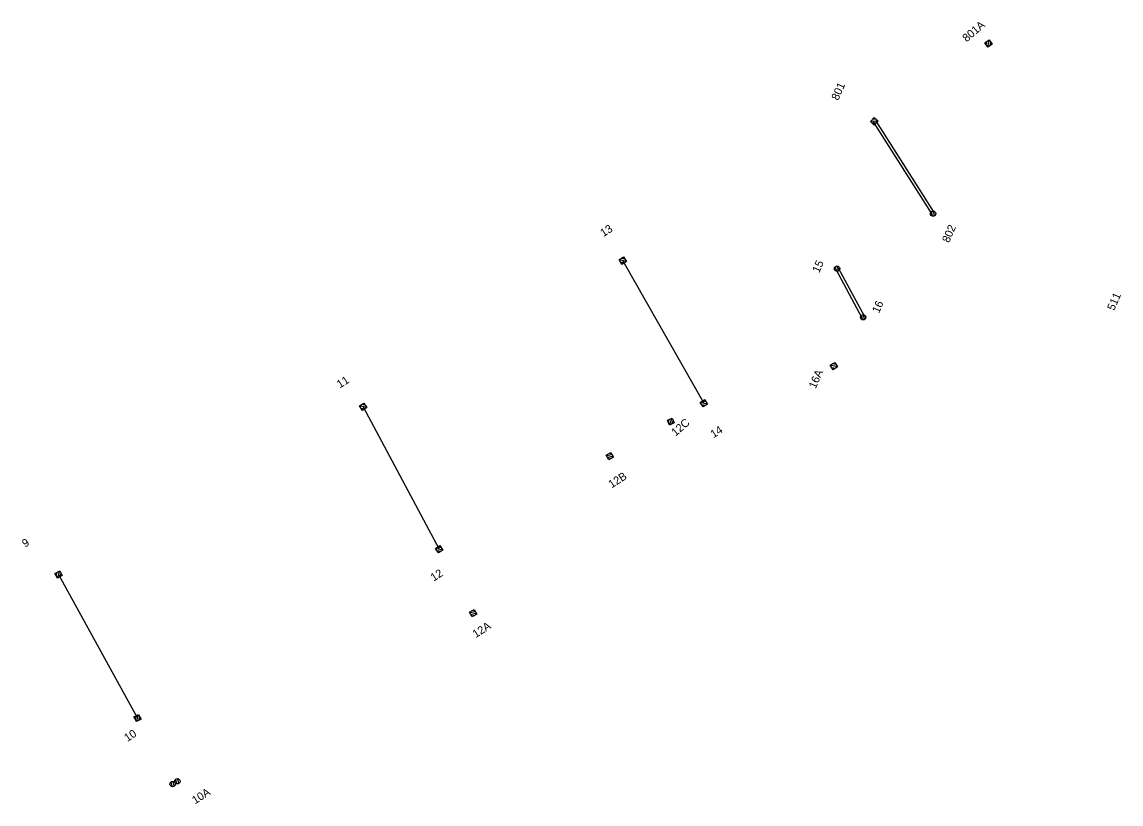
# Model space of a CAD drawing. Extents: x -595867 to -593796, y -1159595 to -1157495.
# Drawn here: x -595653.3 to -595447.3, y -1159453 to -1159306.6 of the extents above; entities that cross this region are included whole.
import ezdxf

# ---------------------------------------------------------------- set-up
doc = ezdxf.new("R2010")
doc.units = 0
doc.layers.add('BVK_kanalizace_jednotna_nova', color=7, linetype='Continuous')

msp = doc.modelspace()

# ---------------------------------------------------------------- linework, layer by layer
at = {"layer": 'BVK_kanalizace_jednotna_nova'}
for p, q in [((-595472.61, -1159310.84), (-595472.48, -1159310.19)), ((-595472.32, -1159311.28), (-595472.04, -1159309.9)), ((-595471.88, -1159310.99), (-595471.75, -1159310.34)), ((-595492.86, -1159325.15), (-595494.27, -1159325.17)), ((-595493.24, -1159324.78), (-595493.91, -1159324.79)), ((-595493.23, -1159325.53), (-595493.89, -1159325.54)), ((-595482.66, -1159342.92), (-595482.82, -1159342.02)), ((-595482.29, -1159342.86), (-595482.45, -1159341.95)), ((-595540.02, -1159351.41), (-595541.4, -1159351.11)), ((-595540.47, -1159351.7), (-595541.11, -1159351.56)), ((-595540.3, -1159350.97), (-595540.96, -1159350.82)), ((-595500.65, -1159353.23), (-595500.81, -1159352.33)), ((-595500.28, -1159353.18), (-595500.44, -1159352.26)), ((-595495.76, -1159362.34), (-595495.92, -1159361.44)), ((-595495.39, -1159362.28), (-595495.56, -1159361.37)), ((-595500.43, -1159371.15), (-595501.81, -1159370.85)), ((-595500.88, -1159371.44), (-595501.52, -1159371.3)), ((-595500.71, -1159370.71), (-595501.37, -1159370.56)), ((-595588.65, -1159378.77), (-595590.03, -1159378.47)), ((-595589.1, -1159379.06), (-595589.74, -1159378.92)), ((-595588.93, -1159378.33), (-595589.59, -1159378.18)), ((-595524.8, -1159378.11), (-595526.18, -1159377.81)), ((-595525.25, -1159378.4), (-595525.89, -1159378.26)), ((-595525.08, -1159377.67), (-595525.74, -1159377.52)), ((-595532.17, -1159381.54), (-595531.91, -1159380.93)), ((-595531.96, -1159382.03), (-595531.42, -1159380.73)), ((-595531.47, -1159381.83), (-595531.22, -1159381.22)), ((-595542.42, -1159388.07), (-595543.78, -1159387.67)), ((-595542.67, -1159387.61), (-595543.31, -1159387.42)), ((-595542.89, -1159388.32), (-595543.52, -1159388.14)), ((-595574.4, -1159405.45), (-595575.78, -1159405.15)), ((-595574.85, -1159405.74), (-595575.49, -1159405.6)), ((-595574.68, -1159405.01), (-595575.34, -1159404.86)), ((-595646.86, -1159410.24), (-595646.67, -1159409.61)), ((-595646.6, -1159410.7), (-595646.2, -1159409.35)), ((-595646.14, -1159410.45), (-595645.95, -1159409.81)), ((-595568.06, -1159417.46), (-595569.42, -1159417.06)), ((-595568.53, -1159417.71), (-595569.16, -1159417.53)), ((-595568.31, -1159417), (-595568.96, -1159416.81)), ((-595632.07, -1159437.11), (-595631.88, -1159436.48)), ((-595631.82, -1159437.58), (-595631.41, -1159436.23)), ((-595631.36, -1159437.34), (-595631.16, -1159436.7)), ((-595625.14, -1159449.74), (-595625.3, -1159448.84)), ((-595624.77, -1159449.68), (-595624.94, -1159448.77)), ((-595624.26, -1159449.23), (-595624.42, -1159448.33)), ((-595623.89, -1159449.18), (-595624.06, -1159448.26))]:
    msp.add_line(p, q, dxfattribs=at)
for points in [[(-595472.87, -1159310.45), (-595472.04, -1159309.9), (-595471.49, -1159310.73), (-595472.32, -1159311.28)], [(-595493.56, -1159325.87), (-595494.28, -1159325.17), (-595493.58, -1159324.45), (-595492.86, -1159325.15)], [(-595540.86, -1159351.95), (-595541.4, -1159351.11), (-595540.56, -1159350.57), (-595540.02, -1159351.41)], [(-595501.27, -1159371.69), (-595501.81, -1159370.85), (-595500.97, -1159370.31), (-595500.43, -1159371.15)], [(-595525.64, -1159378.65), (-595526.18, -1159377.81), (-595525.34, -1159377.27), (-595524.8, -1159378.11)], [(-595589.49, -1159379.31), (-595590.03, -1159378.47), (-595589.19, -1159377.93), (-595588.65, -1159378.77)], [(-595532.34, -1159381.11), (-595531.42, -1159380.73), (-595531.04, -1159381.65), (-595531.96, -1159382.04)], [(-595543.3, -1159388.55), (-595543.78, -1159387.67), (-595542.9, -1159387.19), (-595542.42, -1159388.07)], [(-595575.24, -1159405.99), (-595575.78, -1159405.15), (-595574.94, -1159404.61), (-595574.4, -1159405.45)], [(-595647.08, -1159409.83), (-595646.2, -1159409.35), (-595645.72, -1159410.23), (-595646.6, -1159410.71)], [(-595568.94, -1159417.94), (-595569.42, -1159417.06), (-595568.54, -1159416.58), (-595568.06, -1159417.46)], [(-595632.29, -1159436.7), (-595631.41, -1159436.23), (-595630.94, -1159437.12), (-595631.82, -1159437.58)]]:
    msp.add_lwpolyline(points, close=True, dxfattribs=at)
for points in [[(-595472.87, -1159310.45), (-595472.04, -1159309.9), (-595471.49, -1159310.73), (-595472.32, -1159311.28), (-595472.87, -1159310.45)], [(-595493.56, -1159325.87), (-595494.28, -1159325.17), (-595493.58, -1159324.45), (-595492.86, -1159325.15), (-595493.56, -1159325.87)], [(-595493.78, -1159325.29), (-595482.76, -1159342.57)], [(-595493.36, -1159325.03), (-595482.34, -1159342.3)], [(-595540.86, -1159351.95), (-595541.4, -1159351.11), (-595540.56, -1159350.57), (-595540.02, -1159351.41), (-595540.86, -1159351.95)], [(-595540.71, -1159351.26), (-595525.49, -1159377.96)], [(-595500.32, -1159352.63), (-595495.43, -1159361.74)], [(-595500.76, -1159352.87), (-595495.87, -1159361.98)], [(-595501.27, -1159371.69), (-595501.81, -1159370.85), (-595500.97, -1159370.31), (-595500.43, -1159371.15), (-595501.27, -1159371.69)], [(-595525.64, -1159378.65), (-595526.18, -1159377.81), (-595525.34, -1159377.27), (-595524.8, -1159378.11), (-595525.64, -1159378.65)], [(-595589.49, -1159379.31), (-595590.03, -1159378.47), (-595589.19, -1159377.93), (-595588.65, -1159378.77), (-595589.49, -1159379.31)], [(-595589.34, -1159378.62), (-595575.09, -1159405.3)], [(-595532.34, -1159381.11), (-595531.42, -1159380.73), (-595531.04, -1159381.65), (-595531.96, -1159382.04), (-595532.34, -1159381.11)], [(-595543.3, -1159388.55), (-595543.78, -1159387.67), (-595542.9, -1159387.19), (-595542.42, -1159388.07), (-595543.3, -1159388.55)], [(-595575.24, -1159405.99), (-595575.78, -1159405.15), (-595574.94, -1159404.61), (-595574.4, -1159405.45), (-595575.24, -1159405.99)], [(-595647.08, -1159409.83), (-595646.2, -1159409.35), (-595645.72, -1159410.23), (-595646.6, -1159410.71), (-595647.08, -1159409.83)], [(-595646.41, -1159410.03), (-595631.63, -1159436.91)], [(-595568.94, -1159417.94), (-595569.42, -1159417.06), (-595568.54, -1159416.58), (-595568.06, -1159417.46), (-595568.94, -1159417.94)], [(-595632.29, -1159436.7), (-595631.41, -1159436.23), (-595630.94, -1159437.12), (-595631.82, -1159437.58), (-595632.29, -1159436.7)]]:
    msp.add_lwpolyline(points, dxfattribs=at)
for centre in [(-595482.55, -1159342.44), (-595482.55, -1159342.44), (-595500.54, -1159352.75), (-595500.54, -1159352.75), (-595495.65, -1159361.86), (-595495.65, -1159361.86), (-595625.03, -1159449.26), (-595625.03, -1159449.26), (-595624.15, -1159448.75), (-595624.15, -1159448.75)]:
    msp.add_circle(centre, 0.5, dxfattribs=at)

# ---------------------------------------------------------------- texts
for s, rotation, p in [('801A', 40.73, (-595476.26, -1159310.4)), ('801', 66.553, (-595500.31, -1159321.36)), ('13', 32.6933, (-595544.32, -1159346.86)), ('802', 66.553, (-595479.56, -1159348.02)), ('15', 66.553, (-595503.89, -1159353.65)), ('16', 66.553, (-595492.69, -1159361.21)), ('511', 66.553, (-595448.63, -1159360.72)), ('11', 32.6933, (-595593.69, -1159375.2)), ('16A', 66.553, (-595504.56, -1159375.34)), ('12C', 40.73, (-595530.81, -1159384.22)), ('14', 32.6933, (-595523.68, -1159384.53)), ('12B', 32.6933, (-595542.78, -1159393.92)), ('9', 32.6933, (-595652.66, -1159405.02)), ('12', 32.6933, (-595576.12, -1159411.37)), ('12A', 32.6933, (-595568.24, -1159421.96)), ('10', 32.6933, (-595633.52, -1159441.4)), ('10A', 32.6933, (-595620.82, -1159453.08))]:
    msp.add_text(s, height=1.5, rotation=rotation, dxfattribs=at).set_placement(p)

doc.saveas('drawing.dxf')
